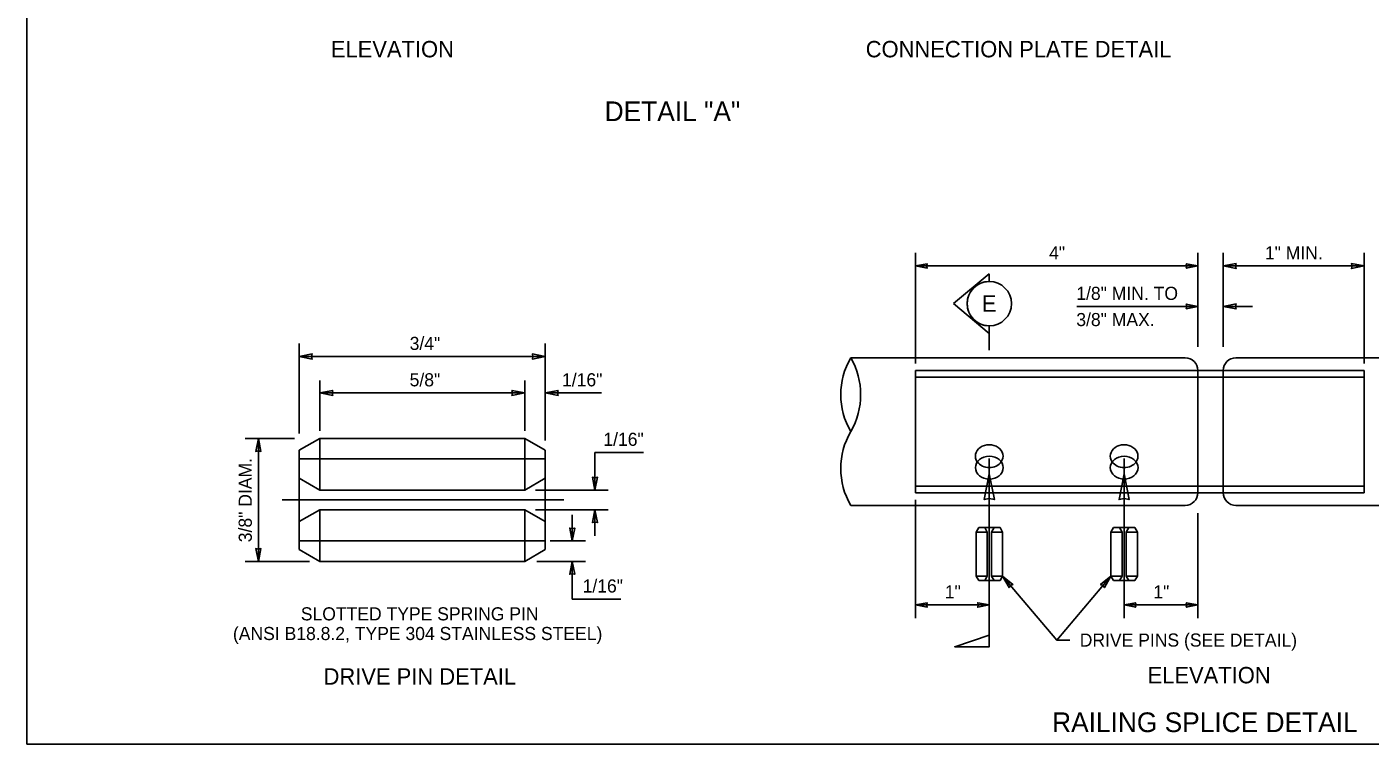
# Model space of a CAD drawing. Extents: x 99862 to 103151, y 100000 to 108076.
# Drawn here: x 99862 to 101501, y 103000 to 103875 of the extents above; entities that cross this region are included whole.
import ezdxf

# ---------------------------------------------------------------- set-up
doc = ezdxf.new("R2010")
doc.units = 0
for name, color, linetype in [('Level 1', 7, 'Continuous'), ('Level 15', 7, 'Continuous'), ('Level 2', 7, 'Continuous'), ('Level 20', 7, 'Continuous'), ('Level 4', 7, 'Continuous'), ('Level 5', 7, 'Continuous'), ('Level 60', 7, 'Continuous'), ('Level 9', 7, 'Continuous')]:
    doc.layers.add(name, color=color, linetype=linetype)

msp = doc.modelspace()

# ---------------------------------------------------------------- linework, layer by layer
at = {"layer": 'Level 1'}
msp.add_lwpolyline([(99862, 102999.5), (103151, 102999.5), (103151, 105075.5), (99862, 105075.5)], close=True, dxfattribs=at)
at = {"layer": 'Level 15'}
for p, q in [((100946.2, 103464), (100946.2, 103599)), ((101290.7, 103484.2), (101290.7, 103599)), ((101321.5, 103484.2), (101321.5, 103599)), ((101493.7, 103464), (101493.7, 103599)), ((100946.2, 103583), (101290.7, 103583)), ((101321.5, 103583), (101493.7, 103583)), ((101143, 103533.6), (101290.7, 103533.6)), ((101321.5, 103533.6), (101357.1, 103533.6)), ((100194.4, 103378.5), (100194.4, 103488.5)), ((100494.4, 103370.1), (100494.4, 103488.5)), ((100194.4, 103472.5), (100494.4, 103472.5)), ((100219.4, 103381.8), (100219.4, 103443.2)), ((100469.4, 103381.8), (100469.4, 103443.2)), ((100219.4, 103428.1), (100469.4, 103428.1)), ((100494.4, 103428.1), (100563, 103428.1)), ((100128.4, 103372.5), (100188.4, 103372.5)), ((100144.4, 103222.5), (100144.4, 103372.5)), ((100555.1, 103309.5), (100555.1, 103355.5)), ((100555.1, 103355.5), (100614.3, 103355.5)), ((101036.2, 103153.3), (101036.2, 103348.2)), ((101200.7, 103153.3), (101200.7, 103348.2)), ((100482.5, 103309.5), (100571.1, 103309.5)), ((100173.6, 103297.5), (100517.3, 103297.5)), ((100946.2, 103153.3), (100946.2, 103297.6)), ((100482.5, 103285.5), (100571.1, 103285.5)), ((100527.4, 103247.5), (100527.4, 103279.5)), ((100555.1, 103253.5), (100555.1, 103285.5)), ((100500.6, 103247.5), (100543.4, 103247.5)), ((100128.4, 103222.5), (100206.9, 103222.5)), ((100484.1, 103222.5), (100543.4, 103222.5)), ((100527.4, 103176.5), (100527.4, 103222.5)), ((100527.4, 103176.5), (100586.6, 103176.5)), ((101036.2, 103169.3), (100946.2, 103169.3)), ((101290.7, 103169.3), (101200.7, 103169.3))]:
    msp.add_line(p, q, dxfattribs=at)
for points in [[(100946.2, 103583), (100960.4, 103580.2), (100959.7, 103583), (100960.4, 103585.7)], [(101290.7, 103583), (101276.5, 103585.7), (101277.2, 103583), (101276.5, 103580.2)], [(101321.5, 103583), (101337.3, 103579.9), (101336.5, 103583), (101337.3, 103586)], [(101493.7, 103583), (101478, 103586), (101478.7, 103583), (101478, 103579.9)], [(101290.7, 103533.6), (101276.5, 103536.4), (101277.2, 103533.6), (101276.5, 103530.8)], [(101321.5, 103533.6), (101337.3, 103530.5), (101336.5, 103533.6), (101337.3, 103536.7)], [(100194.4, 103472.5), (100210.1, 103469.4), (100209.4, 103472.5), (100210.1, 103475.6)], [(100494.4, 103472.5), (100478.7, 103475.6), (100479.4, 103472.5), (100478.7, 103469.4)], [(100219.4, 103428.1), (100235.1, 103425), (100234.4, 103428.1), (100235.1, 103431.2)], [(100469.4, 103428.1), (100453.7, 103431.2), (100454.4, 103428.1), (100453.7, 103425)], [(100494.4, 103428.1), (100510.1, 103425), (100509.4, 103428.1), (100510.1, 103431.2)], [(100144.4, 103372.5), (100141.3, 103356.8), (100144.4, 103357.5), (100147.5, 103356.8)], [(100555.1, 103309.5), (100558.2, 103325.2), (100555.1, 103324.5), (100552, 103325.2)], [(100555.1, 103285.5), (100552, 103269.8), (100555.1, 103270.5), (100558.2, 103269.8)], [(100527.4, 103247.5), (100530.5, 103263.2), (100527.4, 103262.5), (100524.3, 103263.2)], [(100144.4, 103222.5), (100147.5, 103238.2), (100144.4, 103237.5), (100141.3, 103238.2)], [(100527.4, 103222.5), (100524.3, 103206.8), (100527.4, 103207.5), (100530.5, 103206.8)], [(100946.2, 103169.3), (100960.4, 103166.6), (100959.7, 103169.3), (100960.4, 103172.1)], [(101036.2, 103169.3), (101022.1, 103172.1), (101022.7, 103169.3), (101022.1, 103166.6)], [(101200.7, 103169.3), (101214.8, 103166.6), (101214.2, 103169.3), (101214.8, 103172.1)], [(101290.7, 103169.3), (101276.5, 103172.1), (101277.2, 103169.3), (101276.5, 103166.6)]]:
    msp.add_lwpolyline(points, close=True, dxfattribs=at)
for centre, start, end in [((100945, 103425.9), 150, 210), ((100789.2, 103425.9), 330, 30), ((100945, 103335.9), 150, 210)]:
    msp.add_arc(centre, 90, start, end, dxfattribs=at)
at = {"layer": 'Level 2'}
for p, q in [((100867.1, 103470.9), (101275.2, 103470.9)), ((101337, 103470.9), (101741.6, 103470.9)), ((100946.2, 103306.3), (100946.2, 103455.5)), ((100946.2, 103455.5), (101290.7, 103455.5)), ((100946.2, 103447.5), (101493.7, 103447.5)), ((101290.7, 103306.3), (101290.7, 103455.5)), ((101290.7, 103455.5), (101321.5, 103455.5)), ((101321.5, 103306.3), (101321.5, 103455.5)), ((101321.5, 103455.5), (101493.7, 103455.5)), ((101493.7, 103306.3), (101493.7, 103455.5)), ((100946.2, 103314.3), (101493.7, 103314.3)), ((100946.2, 103306.3), (101290.7, 103306.3)), ((101321.5, 103306.3), (101290.7, 103306.3)), ((101321.5, 103306.3), (101493.7, 103306.3)), ((100867.1, 103290.9), (101275.2, 103290.9)), ((101337, 103290.9), (101741.6, 103290.9))]:
    msp.add_line(p, q, dxfattribs=at)
for centre, start, end in [((101275.2, 103455.5), 0, 90), ((101337, 103455.5), 90, 180), ((101275.2, 103306.3), 270, 360), ((101337, 103306.3), 180, 270)]:
    msp.add_arc(centre, 15.4, start, end, dxfattribs=at)
for centre in [(101036.1, 103350.9), (101200.6, 103350.9)]:
    msp.add_ellipse(centre, major_axis=(16.9, 0), ratio=0.823807, start_param=5.765717, end_param=9.955295, dxfattribs=at)
at = {"layer": 'Level 20'}
for p, q in [((101036.2, 103308.6), (101036.2, 103275.2)), ((101200.7, 103308.6), (101200.7, 103275.2)), ((101290.7, 103153.3), (101290.7, 103281.2)), ((101134.5, 103126.5), (101118.5, 103126.5))]:
    msp.add_line(p, q, dxfattribs=at)
for points in [[(101036.2, 103329.4), (101042.4, 103298), (101036.2, 103299.4), (101030.1, 103298)], [(101200.7, 103329.4), (101206.8, 103298), (101200.7, 103299.4), (101194.5, 103298)], [(101052.4, 103204.5), (101060.2, 103190.5), (101062.1, 103193), (101064.9, 103194.5)], [(101184.5, 103204.5), (101172, 103194.5), (101174.8, 103193), (101176.7, 103190.5)]]:
    msp.add_lwpolyline(points, close=True, dxfattribs=at)
msp.add_lwpolyline([(101052.4, 103204.5), (101118.5, 103126.5), (101184.5, 103204.5)], dxfattribs=at)
at = {"layer": 'Level 4'}
for p, q in [((100194.4, 103358.1), (100219.4, 103372.5)), ((100194.4, 103236.9), (100194.4, 103358.1)), ((100219.4, 103372.5), (100469.4, 103372.5)), ((100219.4, 103309.5), (100219.4, 103372.5)), ((100469.4, 103372.5), (100494.4, 103358.1)), ((100469.4, 103309.5), (100469.4, 103372.5)), ((100494.4, 103236.9), (100494.4, 103358.1)), ((100194.4, 103347.5), (100494.4, 103347.5)), ((100194.4, 103323.9), (100219.4, 103309.5)), ((100219.4, 103309.5), (100469.4, 103309.5)), ((100469.4, 103309.5), (100494.4, 103323.9)), ((100194.4, 103271.1), (100219.4, 103285.5)), ((100219.4, 103285.5), (100469.4, 103285.5)), ((100219.4, 103222.5), (100219.4, 103285.5)), ((100469.4, 103222.5), (100469.4, 103285.5)), ((100469.4, 103285.5), (100494.4, 103271.1)), ((101020.1, 103258.3), (101023.2, 103263.7)), ((101049.3, 103263.7), (101023.2, 103263.7)), ((101033.7, 103258.3), (101030.6, 103263.7)), ((101038.8, 103258.3), (101041.9, 103263.7)), ((101052.4, 103258.3), (101049.3, 103263.7)), ((101184.5, 103258.3), (101187.6, 103263.7)), ((101213.7, 103263.7), (101187.6, 103263.7)), ((101198.1, 103258.3), (101195, 103263.7)), ((101203.3, 103258.3), (101206.4, 103263.7)), ((101216.8, 103258.3), (101213.7, 103263.7)), ((100194.4, 103247.5), (100494.4, 103247.5)), ((101020.1, 103204.5), (101020.1, 103258.3)), ((101033.7, 103258.3), (101020.1, 103258.3)), ((101033.7, 103204.5), (101033.7, 103258.3)), ((101038.8, 103204.5), (101038.8, 103258.3)), ((101052.4, 103258.3), (101038.8, 103258.3)), ((101052.4, 103204.5), (101052.4, 103258.3)), ((101184.5, 103204.5), (101184.5, 103258.3)), ((101198.1, 103258.3), (101184.5, 103258.3)), ((101198.1, 103204.5), (101198.1, 103258.3)), ((101203.3, 103204.5), (101203.3, 103258.3)), ((101216.8, 103258.3), (101203.3, 103258.3)), ((101216.8, 103204.5), (101216.8, 103258.3)), ((100194.4, 103236.9), (100219.4, 103222.5)), ((100469.4, 103222.5), (100494.4, 103236.9)), ((100219.4, 103222.5), (100469.4, 103222.5)), ((101023.2, 103199.1), (101020.1, 103204.5)), ((101033.7, 103204.5), (101020.1, 103204.5)), ((101049.3, 103199.1), (101023.2, 103199.1)), ((101030.6, 103199.1), (101033.7, 103204.5)), ((101052.4, 103204.5), (101038.8, 103204.5)), ((101041.9, 103199.1), (101038.8, 103204.5)), ((101049.3, 103199.1), (101052.4, 103204.5)), ((101187.6, 103199.1), (101184.5, 103204.5)), ((101198.1, 103204.5), (101184.5, 103204.5)), ((101213.7, 103199.1), (101187.6, 103199.1)), ((101195, 103199.1), (101198.1, 103204.5)), ((101216.8, 103204.5), (101203.3, 103204.5)), ((101206.4, 103199.1), (101203.3, 103204.5)), ((101213.7, 103199.1), (101216.8, 103204.5))]:
    msp.add_line(p, q, dxfattribs=at)
at = {"layer": 'Level 5'}
for centre in [(101036.2, 103336.9), (101200.7, 103336.9)]:
    msp.add_ellipse(centre, major_axis=(16.9, 0), ratio=0.823807, dxfattribs=at)
for centre, end_param in [((101036.2, 103350.9), 5.759359), ((101200.7, 103350.9), 5.746142)]:
    msp.add_ellipse(centre, major_axis=(16.9, 0), ratio=0.823807, start_param=3.665604, end_param=end_param, dxfattribs=at)
at = {"layer": 'Level 60'}
msp.add_line((99862, 102999.5), (99862, 102999.5), dxfattribs=at)
at = {"layer": 'Level 9'}
for p, q in [((101036.2, 103573.6), (100992.6, 103537)), ((101036.2, 103564), (101036.2, 103573.6)), ((100992.6, 103537), (101036.2, 103500.5)), ((101036.2, 103500.5), (101036.2, 103510)), ((101036.2, 103510), (101036.2, 103480.2)), ((101036.2, 103153.3), (101036.2, 103118.4))]:
    msp.add_line(p, q, dxfattribs=at)
msp.add_lwpolyline([(101036.2, 103132.4), (100994, 103118.4), (101036.2, 103118.4)], close=True, dxfattribs=at)
msp.add_circle((101036.2, 103537), 27, dxfattribs=at)
msp.add_arc((101036.2, 103537), 27, 89.9978, 270.0022, dxfattribs=at)

# ---------------------------------------------------------------- texts
at = {"layer": 'Level 20'}
for s, height, p in [('ELEVATION', 20, (100232.9, 103837.6)), ('CONNECTION PLATE DETAIL', 20, (100885.4, 103837.6)), ('DETAIL "A"', 24, (100566.9, 103759.8)), ('4"', 16, (101109.1, 103591)), ('1" MIN.', 16, (101372.4, 103591)), ('1/8" MIN. TO', 16, (101142.3, 103541.6)), ('E', 20, (101027.1, 103527.2)), ('3/8" MAX.', 16, (101142.3, 103509.6)), ('3/4"', 16, (100329, 103480.5)), ('5/8"', 16, (100329, 103436.1)), ('1/16"', 16, (100514.9, 103436.1)), ('1/16"', 16, (100565.3, 103363.5)), ('1/16"', 16, (100540, 103184.5)), ('1"', 16, (100981.9, 103177.3)), ('1"', 16, (101236.3, 103177.3)), ('SLOTTED TYPE SPRING PIN', 16, (100196.2, 103150.5)), ('(ANSI B18.8.2, TYPE 304 STAINLESS STEEL)', 16, (100113.4, 103126.5)), ('DRIVE PINS (SEE DETAIL)', 16, (101146.5, 103118.5)), ('DRIVE PIN DETAIL', 20, (100224, 103072.1)), ('ELEVATION', 20, (101229.3, 103073.7)), ('RAILING SPLICE DETAIL', 24, (101112.8, 103014.2))]:
    msp.add_text(s, height=height, dxfattribs=at).set_placement(p)
msp.add_text('3/8" DIAM.', height=16, rotation=90, dxfattribs=at).set_placement((100136.4, 103245.9))

doc.saveas('drawing.dxf')
